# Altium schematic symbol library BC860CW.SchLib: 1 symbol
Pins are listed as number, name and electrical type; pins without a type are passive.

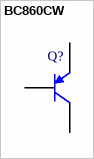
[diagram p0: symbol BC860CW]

## BC860CW
designator Q?
PNP Silicon AF Transistor, 45 V VCEO, 100 mA IC, SOT323, Reel, Green; Manufacturer: Infineon; PartNumber: BC860CW; fT (typ): 250 MHz; Green: TRUE; IC: 2 mA; IC (max): 100 mA; ICBO (max): 15 nA; ICM (max): 200 mA; VCBO (max): 50 V; VCE: 5 V; VCEO (max): 45 V
footprint INF-SOT323_N (SOT23, 3-Leads, Body 2x1.25 mm, Pitch 0.65 mm, IPC Medium Density)
footprint INF-SOT323_L (SOT23, 3-Leads, Body 2x1.25 mm, Pitch 0.65 mm, IPC High Density)
footprint INF-SOT323_M (SOT23, 3-Leads, Body 2x1.25 mm, Pitch 0.65 mm, IPC Low Density)
pins: 1 B, 2 E, 3 C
